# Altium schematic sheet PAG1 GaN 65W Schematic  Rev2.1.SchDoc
size 482 x 279 mm; PageSetup: Record=PageOptions¦CenterHorizontal=True¦CenterVertical=True¦PrintScale=0.61¦XCorrection=1.00¦YCorrection=1.00¦PrintKind=0¦BorderSize=5000000¦LeftOffset=0¦BottomOffset=0¦Orientation=2¦PaperLength=1000¦PaperWidth=1000¦Scale=100¦PaperSource=7¦PrintQuality=-4¦MediaType=1¦DitherType=10¦PaperKind=A4¦PrintScaleMode=1
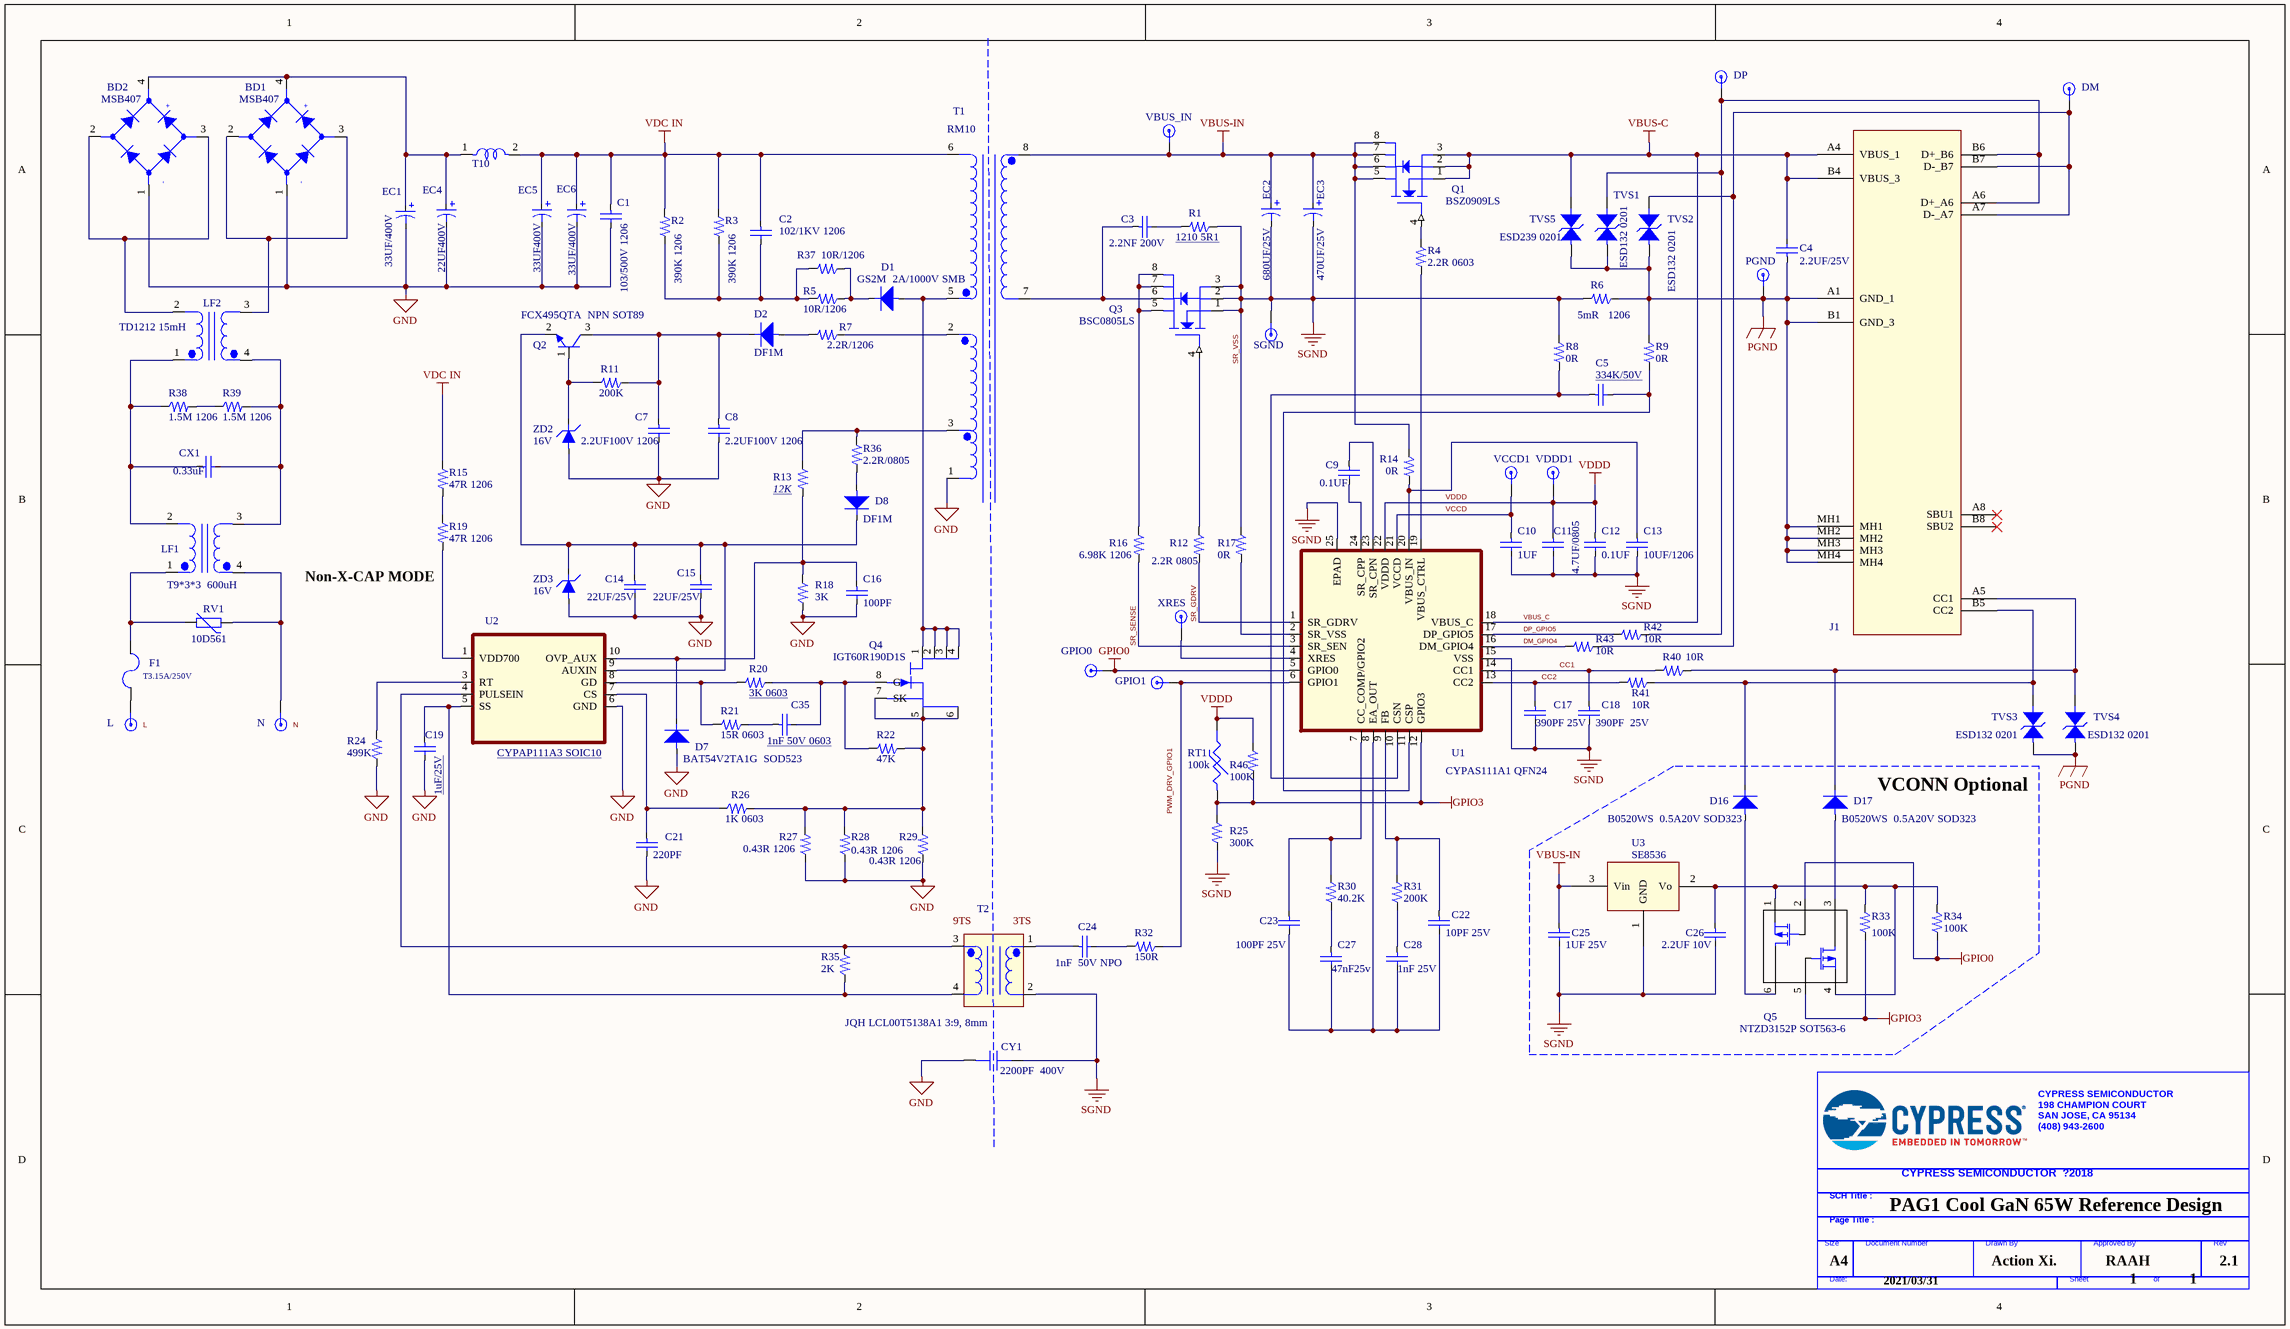
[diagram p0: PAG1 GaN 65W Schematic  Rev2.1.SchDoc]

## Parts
(Parts that share a designator on the sheet are numbered #1, #2 ... from top to bottom, then left to right.)
?#1  T10  [T11]
?#2  CyTitleBlock_2018  (value not drawn)  (graphical)
BD1  MSB407  [BD(DB106)]
BD2  MSB407  [BD(DB106)]
C1  103/500V 1206  [R1206]
C2  102/1KV 1206  [R1206]
C3  2.2NF 200V  [R1206]
C4  2.2UF/25V  [WS0603]
C5  334K/50V  [WS0603]
C7  2.2UF100V 1206  [R1206]
C8  2.2UF100V 1206  [r1206]
C9  0.1UF  [WS0603]
C10  1UF  [WS0603]
C11  4.7UF/0805  [WS0603]
C12  0.1UF  [WS0603]
C13  10UF/1206  [R0603]
C14  22UF/25V  [WS0805]
C15  22UF/25V  [WS0805]
C16  100PF  [WS0603]
C17  390PF 25V  [WS0603]
C18  390PF  25V  [WS0603]
C19  1uF/25V  [WS0603]
C21  220PF  [WS0603]
C22  10PF 25V  [WS0603]
C23  100PF 25V  [WS0603]
C24  1nF  50V NPO  [WS0603]
C25  1UF 25V  [WS0603]
C26  2.2UF 10V  [WS0603]
C27  47nF25v  [WS0603]
C28  1nF 25V  [WS0603]
C35  1nF 50V 0603  [R0603]
CX1  0.33uF  [CX12.5]
CY1  2200PF  400V  [CAP10Y1]
D1  GS2M  2A/1000V SMB  [SMA]
D2  DF1M  [SOD-123/LL-34-T]
D7  BAT54V2TA1G  SOD523  [SOD-323-R]
D8  DF1M  [SOD-123/LL-34-T]
D16  B0520WS  0.5A20V SOD323  [SOD-323]
D17  B0520WS  0.5A20V SOD323  [SOD-323]
DM  (no value)
DP  (no value)
EC1  33UF/400V  [EC10]
EC2  680UF/25V  [EC8-5]
EC3  470UF/25V  [EC6-2.5]
EC4  22UF400V  [EC8-5]
EC5  33UF400V  [EC10]
EC6  33UF/400V  [EC10]
F1  T3.15A/250V  [FUSE2]
GPIO0  (no value)
GPIO1  (no value)
J1  (no value)  [type-c3]
L  (no value)
LF1  T9*3*3  600uH  [T9*5*3]
LF2  TD1212 15mH  [TD15 20*11]
N  (no value)
PGND  (no value)
Q1  BSZ0909LS  [PPAK3*3]
Q2  FCX495QTA  NPN SOT89  [SOT89]
Q3  BSC0805LS  [PPAK3*3]
Q4  IGT60R190D1S  [DFN8*8_IGLD60R190D1]
Q5  NTZD3152P SOT563-6  [SOT-563]
R1  1210 5R1  [WS1210]
R2  390K 1206  [R1206]
R3  390K 1206  [R1206]
R4  2.2R 0603  [WS0603]
R5  10R/1206  [R1206]
R6  5mR   1206  [R1206]
R7  2.2R/1206  [R1206]
R8  0R  [WS0603]
R9  0R  [WS0603]
R11  200K  [r0603]
R12  2.2R 0805  [WS0603]
R13  12K  [R0805]
R14  0R  [WS0603]
R15  47R 1206  [R1206]
R16  6.98K 1206  [R1206]
R17  0R  [WS0603]
R18  3K  [WS0603]
R19  47R 1206  [R1206]
R20  3K 0603  [WS0603]
R21  15R 0603  [WS0603]
R22  47K  [WS0603]
R24  499K  [WS0603]
R25  300K  [WS0603]
R26  1K 0603  [WS0603]
R27  0.43R 1206  [R1206]
R28  0.43R 1206  [R1206]
R29  0.43R 1206  [R1206]
R30  40.2K  [WS0603]
R31  200K  [WS0603]
R32  150R  [WS0603]
R33  100K  [WS0603]
R34  100K  [WS0603]
R35  2K  [WS0603]
R36  2.2R/0805  [R0805]
R37  10R/1206  [R1206]
R38  1.5M 1206  [R1206]
R39  1.5M 1206  [R1206]
R40  10R  [WS0603]
R41  10R  [WS0603]
R42  10R  [WS0603]
R43  10R  [WS0603]
R46  100K  [WS0603]
RT1  100k  [ws0603]
RV1  10D561  [MOV10D471]
SGND  (no value)
T1  RM10  [RM10-3]
T2  JQH LCL00T5138A1 3:9, 8mm  [Pulse Transformer]
TVS1  ESD132 0201  [R0201]
TVS2  ESD132 0201  [R0201]
TVS3  ESD132 0201  [R0201]
TVS4  ESD132 0201  [R0201]
TVS5  ESD239 0201  [R0201]
U1  CYPAS111A1 QFN24  [QFN24 cypd]
U2  CYPAP111A3 SOIC10  [SO-10]
U3  SE8536  [SOT-23]
VBUS_IN  (no value)
VCCD1  (no value)
VDDD1  (no value)
XRES  (no value)
ZD2  16V  [SOD-123/LL-34-T]
ZD3  16V  [SOD-123/LL-34-T]

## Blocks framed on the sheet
VCONN Optional: C25 C26 D16 D17 Q5 R33 R34 U3

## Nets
GND: BD1.1(DC_OUT_PLUS) BD2.1(DC_OUT_PLUS) C1.2 C7.2 C8.2 C14.2 C15.2 C16.2 C19.2 C21.2 CY1.1 D7.1 EC1.2 EC4.2 EC5.2 EC6.2 R18.2 R24.2 R27.1 R28.1 R29.1 T1.1(IN1) U2.6(GND) ZD2.1 ZD3.1
GPIO0: GPIO0.1 Q5.2 R34.1 U1.5(GPIO0)
GPIO3: Q5.5 R25.1 R33.1 R46.2 RT1.1 U1.12(GPIO3)
PGND: C4.1 J1.A1(GND_1) J1.B1(GND_3) J1.MH1 J1.MH2 J1.MH3 J1.MH4 PGND.1 R6.1 R9.2 TVS1.2(CC1) TVS2.2(CC1) TVS3.2(CC1) TVS4.2(CC1) TVS5.2(CC1)
SR_VSS: C10.2 C11.2 C12.2 C13.2 C17.2 C18.2 C25.2 C26.2 CY1.2 EC2.2 EC3.2 Q3.1(S) Q3.2(S) Q3.3(S) R1.1 R6.2 R8.2 R17.1 R25.2 SGND.1 T2.2 U1.15(VSS) U1.25(EPAD) U3.1(GND)  [also labelled SGND]
VBUS-IN: C25.1 EC2.1 EC3.1 Q1.5(D) Q1.6(D) Q1.7(D) Q1.8(D) R14.2 T1.8(OUT1) U3.3(Vin) VBUS_IN.1
VBUS_C: C4.2 J1.A4(VBUS_1) J1.B4(VBUS_3) Q1.1(S) Q1.2(S) Q1.3(S) TVS5.1(CC2) U1.18(VBUS_C)  [also labelled VBUS-C]
VDC IN: ?#1.2 C1.1 C2.1 EC5.1 EC6.1 R2.2 R3.2 R15.1 T1.6(AUX1)
VDDD: C11.1 C12.1 R46.1 RT1.2 U1.22(VDDD) VDDD1.1
CC1: C18.1 R40.2 U1.14(CC1)
CC2: C17.1 R41.2 U1.13(CC2)
DM_GPIO4: R43.2 U1.16(DM_GPIO4)
DP_GPIO5: R42.2 U1.17(DP_GPIO5)
SR_GDRV: R12.2 U1.1(SR_GDRV)
SR_SENSE: R16.2 U1.3(SR_SEN)
VCCD: C10.1 U1.21(VCCD) VCCD1.1
Net?#1_1: ?#1.1 BD1.4(DC_OUT_MINUS) BD2.4(DC_OUT_MINUS) EC1.1 EC4.1
NetBD1_2: BD1.2(AC_IN_2) BD1.3(AC_IN_1) LF2.3
NetBD2_2: BD2.2(AC_IN_2) BD2.3(AC_IN_1) LF2.2
NetC2_2: C2.2 R2.1 R3.1 R5.2 R37.2
NetC3_1: C3.1 Q3.6(D) T1.7(OUT3)
NetC3_2: C3.2 R1.2
NetC5_1: C5.1 R8.1 U1.10(CSN)
NetC5_2: C5.2 R9.1 U1.11(CSP)
NetC7_1: C7.1 C8.1 D2.2 Q2.3(C) R11.1
NetC9_1: C9.1 U1.23(SR_CPN)
NetC9_2: C9.2 U1.24(SR_CPP)
NetC13_1: C13.1 R14.1 U1.20(VBUS_IN)
NetC14_1: C14.1 C15.1 D8.2 Q2.2(E) U2.9(AUXIN) ZD3.2
NetC16_1: C16.1 D7.2 R13.2 R18.1 U2.10(OVP_AUX)
NetC19_1: C19.1 R35.2 T2.4 U2.5(SS)
NetC21_1: C21.1 R26.1 U2.7(CS)
NetC22_1: C22.1 R31.2 U1.9(FB)
NetC22_2: C22.2 C23.2 C27.2 C28.2 U1.8(EA_OUT)
NetC23_1: C23.1 R30.2 U1.7(CC_COMP/GPIO2)
NetC24_1: C24.1 T2.1
NetC24_2: C24.2 R32.2
NetC26_1: C26.1 Q5.1 Q5.4 R33.2 R34.2 U3.2(Vo)
NetC27_1: C27.1 R30.1
NetC28_1: C28.1 R31.1
NetC35_1: C35.1 R21.1
NetC35_2: C35.2 Q4.8(G) R20.1 R22.2
NetCX1_1: CX1.1 LF1.2 LF2.1 R38.1
NetCX1_2: CX1.2 LF1.3 LF2.4 R39.2
NetD1_A: D1.A Q4.1(S) Q4.2(S) Q4.3(S) Q4.4(S) T1.5(AUX2)
NetD1_K: D1.K R5.1 R37.1
NetD2_1: D2.1 R7.2
NetD8_1: D8.1 R36.2
NetD16_A: D16.A Q5.6
NetD16_K: D16.K J1.B5(CC2) R41.1 TVS3.1(CC2)
NetD17_A: D17.A Q5.3
NetD17_K: D17.K J1.A5(CC1) R40.1 TVS4.1(CC2)
NetDM_1: DM.1 J1.A7(D-_A7) J1.B7(D-_B7) R43.1 TVS2.1(CC2)
NetDP_1: DP.1 J1.A6(D+_A6) J1.B6(D+_B6) R42.1 TVS1.1(CC2)
NetF1_1: F1.1 L.1
NetF1_2: F1.2 LF1.1 RV1.1
NetGPIO1_1: GPIO1.1 R32.1 U1.6(GPIO1)
NetLF1_4: LF1.4 N.1 RV1.2
NetQ1_4: Q1.4(G) R4.1
NetQ2_1: Q2.1(B) R11.2 ZD2.2
NetQ3_4: Q3.4(G) R12.1
NetQ3_5: Q3.5(D) Q3.7(D) Q3.8(D) R16.1
NetQ4_5: Q4.5(S) Q4.6(S) Q4.7(SK) R22.1 R26.2 R27.2 R28.2 R29.2
NetR4_2: R4.2 U1.19(VBUS_CTRL)
NetR7_1: R7.1 T1.2(AUX3)
NetR13_1: R13.1 R36.1 T1.3(IN2)
NetR15_2: R15.2 R19.1
NetR17_2: R17.2 U1.2(SR_VSS)
NetR19_2: R19.2 U2.1(VDD700)
NetR20_2: R20.2 R21.2 U2.8(GD)
NetR24_1: R24.1 U2.3(RT)
NetR35_1: R35.1 T2.3 U2.4(PULSEIN)
NetR38_2: R38.2 R39.1
NetU1_4: U1.4(XRES) XRES.1

Not connected (* = marked no-connect by the designer): J1 A8(SBU1)* A9(VBUS_2) A12(GND_2) B8(SBU2)* B9(VBUS_4) B12(GND_4); T1 11(Clip_pin)

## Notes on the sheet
- (near R19) Non-X-CAP MODE
- PAG1 Cool GaN 65W Reference Design
- A4
- 2021/03/31
- Action Xi.
- RAAH
- 1
- 2.1
- Labels drawn without touching a wire or pin: 3TS, 9TS, L, N, PWM_DRV_GPIO1

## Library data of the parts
?#1 = INDUCTOR: 电感
BD1 BD2 = BR805D_1
C1-C5 C7-C19 C21-C28 C35 CX1 = CAP1: 电容
CY1 = 0_0.01uF-50V-10%-X7R-0603: C35: C9
D1 D2 D7 D8 D16 D17 = DIODE: 二极管
DM DP GPIO0 GPIO1 L N PGND SGND VBUS_IN VCCD1 VDDD1 XRES = TEST_POINT
EC1-EC6 = CAP2: 电解电容
F1 = FUSE1
J1 = USB-PD_TYPE-C_7
LF1 LF2 = INDUCTOR IRON_8
Q1 = DMTH10H010LCT_5
Q2 = NPN
Q3 = MOSFET_N
Q4 = IGT60R190D1S: Cool GaN PG-LSON-8
Q5 = MOS PNP-563
R1-R9 R11-R22 R24-R43 R46 = RES2: 电阻
RT1 = RESISTOR VAR 2_4
RV1 = VARISTOR
T1 = PA5222NL_24
T2 = TRANSFORMER_11
TVS1-TVS5 = TVS Diode_1
U1 = PAG1S_11
U2 = PAG1P_3
U3 = ASO241-NO-SPST_0
ZD2 ZD3 = ZD1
